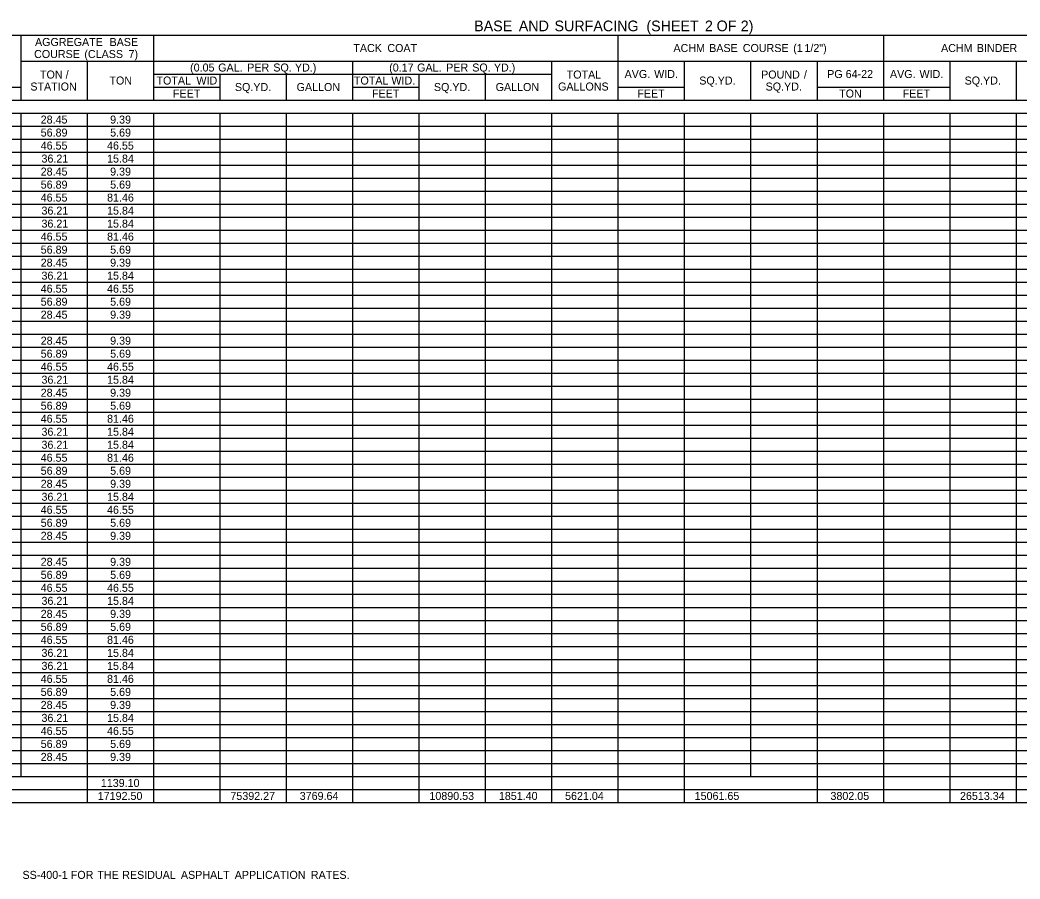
# Model space of a CAD drawing. Extents: x 977434 to 989596, y 1525697 to 1528336.
# Drawn here: x 984835 to 985434, y 1527595 to 1528110 of the extents above; entities that cross this region are included whole.
import ezdxf

# ---------------------------------------------------------------- set-up
doc = ezdxf.new("R2010")
doc.units = 0
doc.layers.add('Default', color=7, linetype='Continuous')

msp = doc.modelspace()

# ---------------------------------------------------------------- linework, layer by layer
at = {"layer": 'Default'}
for p, q in [((984511.57, 1528101.06), (985869.55, 1528101.06)), ((984835.27, 1528062.06), (984835.27, 1528101.06)), ((984914.83, 1528062.06), (984914.83, 1528101.06)), ((985193.29, 1528062.06), (985193.29, 1528101.06)), ((985352.41, 1528085.46), (985352.41, 1528101.06)), ((985352.41, 1528062.06), (985352.41, 1528101.06)), ((984835.27, 1528085.46), (985869.55, 1528085.46)), ((984875.05, 1528062.06), (984875.05, 1528085.46)), ((985034.17, 1528062.06), (985034.17, 1528085.46)), ((985153.51, 1528062.06), (985153.51, 1528085.46)), ((985233.07, 1528062.06), (985233.07, 1528085.46)), ((985272.85, 1528062.06), (985272.85, 1528085.46)), ((985312.63, 1528062.06), (985312.63, 1528085.46)), ((985392.19, 1528062.06), (985392.19, 1528085.46)), ((985431.97, 1528062.06), (985431.97, 1528085.46)), ((984914.83, 1528077.66), (985153.51, 1528077.66)), ((984954.61, 1528062.06), (984954.61, 1528077.66)), ((984994.39, 1528062.06), (984994.39, 1528077.66)), ((985073.95, 1528062.06), (985073.95, 1528077.66)), ((985113.73, 1528062.06), (985113.73, 1528077.66)), ((984795.49, 1528069.86), (984835.27, 1528069.86)), ((984835.27, 1528062.06), (984835.27, 1528069.86)), ((984914.83, 1528069.86), (984954.61, 1528069.86)), ((984954.61, 1528062.06), (984954.61, 1528069.86)), ((985034.17, 1528069.86), (985073.95, 1528069.86)), ((985073.95, 1528062.06), (985073.95, 1528069.86)), ((985193.29, 1528069.86), (985233.07, 1528069.86)), ((985233.07, 1528062.06), (985233.07, 1528069.86)), ((985312.63, 1528069.86), (985392.19, 1528069.86)), ((985392.19, 1528062.06), (985392.19, 1528069.86)), ((984511.57, 1528062.06), (985869.55, 1528062.06)), ((984835.27, 1528062.06), (984954.61, 1528062.06)), ((984954.61, 1528062.06), (985073.95, 1528062.06)), ((985073.95, 1528062.06), (985113.73, 1528062.06)), ((985113.73, 1528062.06), (985233.07, 1528062.06)), ((985233.07, 1528062.06), (985392.19, 1528062.06)), ((985392.19, 1528062.06), (985551.31, 1528062.06)), ((984511.57, 1528054.26), (985869.55, 1528054.26)), ((984835.27, 1527656.46), (984835.27, 1528054.26)), ((984835.27, 1527656.46), (984835.27, 1528054.26)), ((984875.05, 1527640.86), (984875.05, 1528054.26)), ((984875.05, 1527640.86), (984875.05, 1528054.26)), ((984914.83, 1527664.26), (984914.83, 1528054.26)), ((984914.83, 1527640.86), (984914.83, 1528054.26)), ((984954.61, 1527640.86), (984954.61, 1528054.26)), ((984954.61, 1527640.86), (984954.61, 1528054.26)), ((984994.39, 1527640.86), (984994.39, 1528054.26)), ((984994.39, 1527640.86), (984994.39, 1528054.26)), ((985034.17, 1527640.86), (985034.17, 1528054.26)), ((985034.17, 1527640.86), (985034.17, 1528054.26)), ((985073.95, 1527640.86), (985073.95, 1528054.26)), ((985073.95, 1527640.86), (985073.95, 1528054.26)), ((985113.73, 1527640.86), (985113.73, 1528054.26)), ((985113.73, 1527640.86), (985113.73, 1528054.26)), ((985153.51, 1527640.86), (985153.51, 1528054.26)), ((985153.51, 1527640.86), (985153.51, 1528054.26)), ((985193.29, 1527640.86), (985193.29, 1528054.26)), ((985193.29, 1527640.86), (985193.29, 1528054.26)), ((985233.07, 1527640.86), (985233.07, 1528054.26)), ((985233.07, 1527640.86), (985233.07, 1528054.26)), ((985272.85, 1527656.46), (985272.85, 1528054.26)), ((985272.85, 1527656.46), (985272.85, 1528054.26)), ((985312.63, 1527640.86), (985312.63, 1528054.26)), ((985312.63, 1527640.86), (985312.63, 1528054.26)), ((985352.41, 1527640.86), (985352.41, 1528054.26)), ((985352.41, 1527640.86), (985352.41, 1528054.26)), ((985392.19, 1527640.86), (985392.19, 1528054.26)), ((985392.19, 1527640.86), (985392.19, 1528054.26)), ((985431.97, 1527640.86), (985431.97, 1528054.26)), ((985431.97, 1527640.86), (985431.97, 1528054.26)), ((984511.57, 1528046.46), (985869.55, 1528046.46)), ((984511.57, 1528038.66), (985869.55, 1528038.66)), ((984511.57, 1528030.86), (985869.55, 1528030.86)), ((984511.57, 1528023.06), (985869.55, 1528023.06)), ((984511.57, 1528015.26), (985869.55, 1528015.26)), ((984511.57, 1528007.46), (985869.55, 1528007.46)), ((984511.57, 1527999.66), (985869.55, 1527999.66)), ((984511.57, 1527991.86), (985869.55, 1527991.86)), ((984511.57, 1527984.06), (985869.55, 1527984.06)), ((984511.57, 1527976.26), (985869.55, 1527976.26)), ((984511.57, 1527968.46), (985869.55, 1527968.46)), ((984511.57, 1527960.66), (985869.55, 1527960.66)), ((984511.57, 1527952.86), (985869.55, 1527952.86)), ((984511.57, 1527945.06), (985869.55, 1527945.06)), ((984511.57, 1527937.26), (985869.55, 1527937.26)), ((984511.57, 1527929.46), (985869.55, 1527929.46)), ((984511.57, 1527921.66), (985869.55, 1527921.66)), ((984511.57, 1527913.86), (985869.55, 1527913.86)), ((984511.57, 1527906.06), (985869.55, 1527906.06)), ((984511.57, 1527898.26), (985869.55, 1527898.26)), ((984511.57, 1527890.46), (985869.55, 1527890.46)), ((984511.57, 1527882.66), (985869.55, 1527882.66)), ((984511.57, 1527874.86), (985869.55, 1527874.86)), ((984511.57, 1527867.06), (985869.55, 1527867.06)), ((984511.57, 1527859.26), (985869.55, 1527859.26)), ((984511.57, 1527851.46), (985869.55, 1527851.46)), ((984511.57, 1527843.66), (985869.55, 1527843.66)), ((984511.57, 1527835.86), (985869.55, 1527835.86)), ((984511.57, 1527828.06), (985869.55, 1527828.06)), ((984511.57, 1527820.26), (985869.55, 1527820.26)), ((984511.57, 1527812.46), (985869.55, 1527812.46)), ((984511.57, 1527804.66), (985869.55, 1527804.66)), ((984511.57, 1527796.86), (985869.55, 1527796.86)), ((984511.57, 1527789.06), (985869.55, 1527789.06)), ((984511.57, 1527781.26), (985869.55, 1527781.26)), ((984511.57, 1527773.46), (985869.55, 1527773.46)), ((984511.57, 1527765.66), (985869.55, 1527765.66)), ((984511.57, 1527757.86), (985869.55, 1527757.86)), ((984511.57, 1527750.06), (985869.55, 1527750.06)), ((984511.57, 1527742.26), (985869.55, 1527742.26)), ((984511.57, 1527734.46), (985869.55, 1527734.46)), ((984511.57, 1527726.66), (985869.55, 1527726.66)), ((984511.57, 1527718.86), (985869.55, 1527718.86)), ((984511.57, 1527711.06), (985869.55, 1527711.06)), ((984511.57, 1527703.26), (985869.55, 1527703.26)), ((984511.57, 1527695.46), (985869.55, 1527695.46)), ((984511.57, 1527687.66), (985869.55, 1527687.66)), ((984511.57, 1527679.86), (985869.55, 1527679.86)), ((984511.57, 1527672.06), (985869.55, 1527672.06)), ((984511.57, 1527664.26), (985869.55, 1527664.26)), ((984511.57, 1527656.46), (985869.55, 1527656.46)), ((984914.83, 1527640.86), (984914.83, 1527656.46)), ((984511.57, 1527648.66), (985869.55, 1527648.66)), ((984511.57, 1527640.86), (985869.55, 1527640.86))]:
    msp.add_line(p, q, dxfattribs=at)

# ---------------------------------------------------------------- texts
for s, height, p in [('BASE', 6.4, (985106.83, 1528103.32)), (' AND', 6.4, (985131.23, 1528103.32)), (' SURFACING', 6.4, (985152.65, 1528103.32)), (' (SHEET', 6.4, (985207.75, 1528103.32)), (' 2', 6.4, (985242.84, 1528103.32)), (' OF', 6.4, (985249.85, 1528103.32)), (' 2)', 6.4, (985264.33, 1528103.32)), ('AGGREGATE', 4.8, (984843.52, 1528094.46)), (' BASE', 4.8, (984886.42, 1528094.46)), ('TACK', 4.8, (985034.39, 1528090.86)), (' COAT', 4.8, (985053.01, 1528090.86)), ('ACHM', 4.8, (985226.35, 1528090.86)), (' BASE', 4.8, (985245.99, 1528090.86)), (' COURSE', 4.8, (985266.15, 1528090.86)), (' (1', 4.8, (985296.38, 1528090.86)), (' 1/2")', 4.8, (985303.11, 1528090.86)), ('ACHM', 4.8, (985386.83, 1528090.86)), (' BINDER', 4.8, (985406.47, 1528090.86)), ('COURSE', 4.8, (984842.95, 1528087.26)), (' (CLASS', 4.8, (984871.32, 1528087.26)), (' 7)', 4.8, (984897.82, 1528087.26)), ('(0.05', 4.8, (984936.5, 1528079.16)), (' GAL.', 4.8, (984951.58, 1528079.16)), (' PER', 4.8, (984969, 1528079.16)), (' SQ.', 4.8, (984984.62, 1528079.16)), (' YD.)', 4.8, (984997.58, 1528079.16)), ('(0.17', 4.8, (985055.89, 1528079.16)), (' GAL.', 4.8, (985070.87, 1528079.16)), (' PER', 4.8, (985088.29, 1528079.16)), (' SQ.', 4.8, (985103.91, 1528079.16)), (' YD.)', 4.8, (985116.87, 1528079.16)), ('TON', 4.8, (984846.49, 1528074.96)), (' /', 4.8, (984860.11, 1528074.96)), ('TOTAL', 4.8, (985162.33, 1528074.96)), ('AVG.', 4.8, (985197.06, 1528075.26)), (' WID.', 4.8, (985213, 1528075.26)), ('POUND', 4.8, (985278.93, 1528074.96)), (' /', 4.8, (985302.82, 1528074.96)), ('PG', 4.8, (985318.54, 1528075.26)), (' 64-22', 4.8, (985327.83, 1528075.26)), ('AVG.', 4.8, (985356.18, 1528075.26)), (' WID.', 4.8, (985372.12, 1528075.26)), ('STATION', 4.8, (984840.71, 1528067.76)), ('TON', 4.8, (984888.13, 1528071.36)), ('TOTAL', 4.8, (984916.36, 1528071.36)), (' WID', 4.8, (984938.52, 1528071.36)), ('SQ.YD.', 4.8, (984963.37, 1528067.46)), ('GALLON', 4.8, (985000.39, 1528067.46)), ('TOTAL WID.', 4.8, (985034.74, 1528071.36)), ('SQ.YD.', 4.8, (985082.71, 1528067.46)), ('GALLON', 4.8, (985119.73, 1528067.46)), ('GALLONS', 4.8, (985157.17, 1528067.76)), ('SQ.YD.', 4.8, (985241.83, 1528071.36)), ('SQ.YD.', 4.8, (985281.61, 1528067.76)), ('SQ.YD.', 4.8, (985400.95, 1528071.36)), ('FEET', 4.8, (984926.22, 1528063.56)), ('FEET', 4.8, (985045.56, 1528063.56)), ('FEET', 4.8, (985204.68, 1528063.56)), ('TON', 4.8, (985325.71, 1528063.56)), ('FEET', 4.8, (985363.8, 1528063.56)), ('28.45', 4.8, (984846.91, 1528047.96)), ('9.39', 4.8, (984888.57, 1528047.96)), ('56.89', 4.8, (984846.92, 1528040.16)), ('5.69', 4.8, (984888.57, 1528040.16)), ('46.55', 4.8, (984846.91, 1528032.36)), ('46.55', 4.8, (984886.69, 1528032.36)), ('36.21', 4.8, (984847.39, 1528024.56)), ('15.84', 4.8, (984886.72, 1528024.56)), ('28.45', 4.8, (984846.91, 1528016.76)), ('9.39', 4.8, (984888.57, 1528016.76)), ('56.89', 4.8, (984846.92, 1528008.96)), ('5.69', 4.8, (984888.57, 1528008.96)), ('46.55', 4.8, (984846.91, 1528001.16)), ('81.46', 4.8, (984886.71, 1528001.16)), ('36.21', 4.8, (984847.39, 1527993.36)), ('15.84', 4.8, (984886.72, 1527993.36)), ('36.21', 4.8, (984847.39, 1527985.56)), ('15.84', 4.8, (984886.72, 1527985.56)), ('46.55', 4.8, (984846.91, 1527977.76)), ('81.46', 4.8, (984886.71, 1527977.76)), ('56.89', 4.8, (984846.92, 1527969.96)), ('5.69', 4.8, (984888.57, 1527969.96)), ('28.45', 4.8, (984846.91, 1527962.16)), ('9.39', 4.8, (984888.57, 1527962.16)), ('36.21', 4.8, (984847.39, 1527954.36)), ('15.84', 4.8, (984886.72, 1527954.36)), ('46.55', 4.8, (984846.91, 1527946.56)), ('46.55', 4.8, (984886.69, 1527946.56)), ('56.89', 4.8, (984846.92, 1527938.76)), ('5.69', 4.8, (984888.57, 1527938.76)), ('28.45', 4.8, (984846.91, 1527930.96)), ('9.39', 4.8, (984888.57, 1527930.96)), ('28.45', 4.8, (984846.91, 1527915.36)), ('9.39', 4.8, (984888.57, 1527915.36)), ('56.89', 4.8, (984846.92, 1527907.56)), ('5.69', 4.8, (984888.57, 1527907.56)), ('46.55', 4.8, (984846.91, 1527899.76)), ('46.55', 4.8, (984886.69, 1527899.76)), ('36.21', 4.8, (984847.39, 1527891.96)), ('15.84', 4.8, (984886.72, 1527891.96)), ('28.45', 4.8, (984846.91, 1527884.16)), ('9.39', 4.8, (984888.57, 1527884.16)), ('56.89', 4.8, (984846.92, 1527876.36)), ('5.69', 4.8, (984888.57, 1527876.36)), ('46.55', 4.8, (984846.91, 1527868.56)), ('81.46', 4.8, (984886.71, 1527868.56)), ('36.21', 4.8, (984847.39, 1527860.76)), ('15.84', 4.8, (984886.72, 1527860.76)), ('36.21', 4.8, (984847.39, 1527852.96)), ('15.84', 4.8, (984886.72, 1527852.96)), ('46.55', 4.8, (984846.91, 1527845.16)), ('81.46', 4.8, (984886.71, 1527845.16)), ('56.89', 4.8, (984846.92, 1527837.36)), ('5.69', 4.8, (984888.57, 1527837.36)), ('28.45', 4.8, (984846.91, 1527829.56)), ('9.39', 4.8, (984888.57, 1527829.56)), ('36.21', 4.8, (984847.39, 1527821.76)), ('15.84', 4.8, (984886.72, 1527821.76)), ('46.55', 4.8, (984846.91, 1527813.96)), ('46.55', 4.8, (984886.69, 1527813.96)), ('56.89', 4.8, (984846.92, 1527806.16)), ('5.69', 4.8, (984888.57, 1527806.16)), ('28.45', 4.8, (984846.91, 1527798.36)), ('9.39', 4.8, (984888.57, 1527798.36)), ('28.45', 4.8, (984846.91, 1527782.76)), ('9.39', 4.8, (984888.57, 1527782.76)), ('56.89', 4.8, (984846.92, 1527774.96)), ('5.69', 4.8, (984888.57, 1527774.96)), ('46.55', 4.8, (984846.91, 1527767.16)), ('46.55', 4.8, (984886.69, 1527767.16)), ('36.21', 4.8, (984847.39, 1527759.36)), ('15.84', 4.8, (984886.72, 1527759.36)), ('28.45', 4.8, (984846.91, 1527751.56)), ('9.39', 4.8, (984888.57, 1527751.56)), ('56.89', 4.8, (984846.92, 1527743.76)), ('5.69', 4.8, (984888.57, 1527743.76)), ('46.55', 4.8, (984846.91, 1527735.96)), ('81.46', 4.8, (984886.71, 1527735.96)), ('36.21', 4.8, (984847.39, 1527728.16)), ('15.84', 4.8, (984886.72, 1527728.16)), ('36.21', 4.8, (984847.39, 1527720.36)), ('15.84', 4.8, (984886.72, 1527720.36)), ('46.55', 4.8, (984846.91, 1527712.56)), ('81.46', 4.8, (984886.71, 1527712.56)), ('56.89', 4.8, (984846.92, 1527704.76)), ('5.69', 4.8, (984888.57, 1527704.76)), ('28.45', 4.8, (984846.91, 1527696.96)), ('9.39', 4.8, (984888.57, 1527696.96)), ('36.21', 4.8, (984847.39, 1527689.16)), ('15.84', 4.8, (984886.72, 1527689.16)), ('46.55', 4.8, (984846.91, 1527681.36)), ('46.55', 4.8, (984886.69, 1527681.36)), ('56.89', 4.8, (984846.92, 1527673.56)), ('5.69', 4.8, (984888.57, 1527673.56)), ('28.45', 4.8, (984846.91, 1527665.76)), ('9.39', 4.8, (984888.57, 1527665.76)), ('1139.10', 4.8, (984882.99, 1527650.16)), ('17192.50', 4.8, (984881.13, 1527642.36)), ('75392.27', 4.8, (984960.67, 1527642.36)), ('3769.64', 4.8, (985002.24, 1527642.36)), ('10890.53', 4.8, (985080.01, 1527642.36)), ('1851.40', 4.8, (985121.67, 1527642.36)), ('5621.04', 4.8, (985161.36, 1527642.36)), ('15061.65', 4.8, (985239.08, 1527642.36)), ('3802.05', 4.8, (985320.51, 1527642.36)), ('26513.34', 4.8, (985398.18, 1527642.36)), (' SS-400-1', 4.8, (984834.22, 1527595.02)), (' FOR', 4.8, (984863.18, 1527595.02)), (' THE', 4.8, (984879.11, 1527595.02)), (' RESIDUAL', 4.8, (984894.03, 1527595.02)), (' ASPHALT', 4.8, (984929.2, 1527595.02)), (' APPLICATION', 4.8, (984961.49, 1527595.02)), (' RATES.', 4.8, (985007.15, 1527595.02))]:
    msp.add_text(s, height=height, dxfattribs=at).set_placement(p)

doc.saveas('drawing.dxf')
